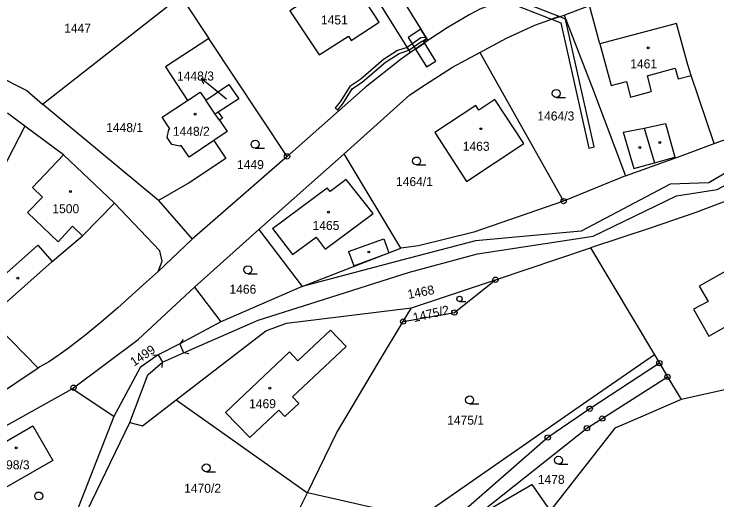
# Model space of a CAD drawing. Extents: x -562167 to -556918, y -1077891 to -1070763.
# Drawn here: x -559876 to -559743.6, y -1075522.9 to -1075431.3 of the extents above; entities that cross this region are included whole.
import ezdxf

# ---------------------------------------------------------------- set-up
doc = ezdxf.new("R2010")
doc.units = 0
for name, color, linetype in [('Hranice parcel', 7, 'Continuous'), ('Parcelní čísla', 7, 'Continuous'), ('Pop  PČ popisy', 7, 'Continuous'), ('Vnitřní kresba', 7, 'Continuous'), ('Věcná břemena k části', 7, 'Continuous'), ('Značky bodu BP', 7, 'Continuous'), ('Značky budov', 7, 'Continuous'), ('Značky kultur', 7, 'Continuous')]:
    doc.layers.add(name, color=color, linetype=linetype)

msp = doc.modelspace()

# ---------------------------------------------------------------- linework, layer by layer
at = {"layer": 'Hranice parcel'}
for p, q in [((-559801.37, -1075438.56), (-559818.39, -1075410.87)), ((-559809.43, -1075417.79), (-559798.08, -1075436.28)), ((-559870.69, -1075448.28), (-559844.66, -1075427.85)), ((-559843.8, -1075429.15), (-559839.36, -1075435.87)), ((-559772.38, -1075431.46), (-559767.63, -1075429.64)), ((-559824.6, -1075458.14), (-559839.36, -1075435.87)), ((-559798.08, -1075436.28), (-559801.37, -1075438.56)), ((-559788.28, -1075438.52), (-559772.5, -1075466.57)), ((-559848.8, -1075466.47), (-559870.69, -1075448.28)), ((-559874.03, -1075452.42), (-559877.3, -1075449.98)), ((-559829.9, -1075471.94), (-559813.82, -1075457.67)), ((-559803.17, -1075475.47), (-559813.82, -1075457.67)), ((-559824.6, -1075458.14), (-559842.46, -1075473.73)), ((-559760.86, -1075461.82), (-559772.5, -1075466.57)), ((-559848.8, -1075466.47), (-559842.46, -1075473.73)), ((-559842.06, -1075482.79), (-559829.9, -1075471.94)), ((-559829.9, -1075471.94), (-559821.79, -1075482.69)), ((-559842.46, -1075473.73), (-559848.9, -1075479.82)), ((-559785.33, -1075481.4), (-559767.4, -1075475.38)), ((-559767.4, -1075475.38), (-559755.39, -1075495.58)), ((-559801.18, -1075486.71), (-559785.33, -1075481.4)), ((-559842.06, -1075482.79), (-559837.1, -1075489.33)), ((-559821.79, -1075482.69), (-559837.1, -1075489.33)), ((-559802.73, -1075489.29), (-559801.18, -1075486.71)), ((-559871.53, -1075498.07), (-559879.99, -1075489.41)), ((-559837.1, -1075489.33), (-559844.81, -1075493.49)), ((-559844.81, -1075493.49), (-559848.92, -1075495.59)), ((-559848.09, -1075496.98), (-559844.1, -1075495.21)), ((-559755.39, -1075495.58), (-559754.46, -1075497.14)), ((-559754.46, -1075497.14), (-559752.93, -1075499.72)), ((-559725.73, -1075498.45), (-559750.37, -1075504.02)), ((-559752.93, -1075499.72), (-559750.37, -1075504.02)), ((-559892.97, -1075517.55), (-559865.07, -1075501.96)), ((-559857.26, -1075507.2), (-559865.07, -1075501.96)), ((-559845.5, -1075504.05), (-559820.78, -1075521.58))]:
    msp.add_line(p, q, dxfattribs=at)
for points in [[(-559672.17, -1075401.69), (-559678.82, -1075405.17), (-559687.43, -1075414.69), (-559699.21, -1075431.72), (-559711.22, -1075442.31), (-559725.64, -1075451.62), (-559745.16, -1075463.14), (-559752.41, -1075463.36), (-559769.21, -1075472.22), (-559789.12, -1075474.06), (-559802.78, -1075477.67), (-559821.79, -1075482.69)], [(-559807.22, -1075432.78), (-559813.19, -1075423.62), (-559824.1, -1075430.68), (-559818.53, -1075439), (-559813.04, -1075435.43), (-559812.51, -1075436.27), (-559807.22, -1075432.78)], [(-559782.91, -1075428.25), (-559788.31, -1075430.38), (-559790.19, -1075431.34), (-559794.42, -1075433.88), (-559798.08, -1075436.28)], [(-559744.13, -1075455.73), (-559748.49, -1075442.88), (-559749.06, -1075440.84), (-559751.22, -1075433.03), (-559765.68, -1075436.89), (-559767.63, -1075429.64)], [(-559788.28, -1075438.52), (-559783.27, -1075435.82), (-559777.89, -1075433.37), (-559775.09, -1075432.34), (-559772.38, -1075431.46)], [(-559772.38, -1075431.46), (-559766.84, -1075445.76), (-559760.86, -1075461.82)], [(-559839.36, -1075435.87), (-559847.51, -1075441.23), (-559843.36, -1075447.56)], [(-559887.86, -1075437.63), (-559885.09, -1075439.61), (-559879.78, -1075442.62), (-559873.64, -1075445.72), (-559870.69, -1075448.28)], [(-559801.37, -1075438.56), (-559803.04, -1075439.72), (-559809.91, -1075445.14), (-559824.6, -1075458.14)], [(-559813.82, -1075457.67), (-559801.47, -1075446.51), (-559798.53, -1075444.57), (-559793.46, -1075441.32), (-559788.28, -1075438.52)], [(-559839.94, -1075447.54), (-559839.56, -1075447.28), (-559835.58, -1075444.55), (-559833.67, -1075447.28), (-559837.59, -1075449.81)], [(-559744.13, -1075455.73), (-559741, -1075454.58), (-559727.67, -1075445.41)], [(-559843.36, -1075447.56), (-559841, -1075445.99), (-559839.94, -1075447.54)], [(-559838.4, -1075455.13), (-559843.08, -1075458.27), (-559844.57, -1075456.05), (-559844.78, -1075456.19), (-559846.32, -1075455.89), (-559847.17, -1075454.56), (-559846.87, -1075453.08), (-559846.67, -1075452.95), (-559848.15, -1075450.75), (-559843.36, -1075447.56)], [(-559837.59, -1075449.81), (-559838.13, -1075450.16), (-559839.94, -1075447.54)], [(-559789.01, -1075448.56), (-559796.77, -1075453.62), (-559790.77, -1075462.85), (-559779.99, -1075455.73), (-559785.43, -1075447.41), (-559788.46, -1075449.39), (-559789.01, -1075448.56)], [(-559837.59, -1075449.81), (-559836.79, -1075450.95), (-559837.34, -1075451.32), (-559835.87, -1075453.44), (-559838.4, -1075455.13)], [(-559874.03, -1075452.42), (-559877.37, -1075458.89), (-559882, -1075465.36), (-559886.93, -1075468.85), (-559882.21, -1075475.68), (-559886.64, -1075478.78), (-559881.95, -1075484.08), (-559879.25, -1075487.14), (-559868.87, -1075477.98), (-559863.12, -1075473.13), (-559857.13, -1075466.97)], [(-559857.13, -1075466.97), (-559866.72, -1075457.84), (-559874.03, -1075452.42)], [(-559844.1, -1075495.21), (-559830.08, -1075489.03), (-559818.93, -1075485.49), (-559801.52, -1075479.98), (-559788.72, -1075476.53), (-559766.9, -1075473.16), (-559751.24, -1075465.57), (-559743.59, -1075464.38), (-559725.67, -1075454.86)], [(-559838.4, -1075455.13), (-559836.16, -1075458.53), (-559843.03, -1075463.12), (-559848.8, -1075466.47)], [(-559760.86, -1075461.82), (-559750.16, -1075457.96), (-559744.13, -1075455.73)], [(-559724.34, -1075460.86), (-559728.19, -1075461.37), (-559747.61, -1075468.71), (-559755.99, -1075471.62), (-559767.4, -1075475.38)], [(-559848.9, -1075479.82), (-559848.16, -1075477.93), (-559848.58, -1075475.94), (-559857.13, -1075466.97)], [(-559772.5, -1075466.57), (-559789.39, -1075472.45), (-559799.82, -1075475.03), (-559803.17, -1075475.47)], [(-559821.79, -1075482.69), (-559813.21, -1075479.34), (-559803.17, -1075475.47)], [(-559746.94, -1075482.59), (-559745.27, -1075485.5), (-559748.02, -1075486.98), (-559745.16, -1075492.02), (-559731.16, -1075484.12), (-559734.28, -1075478.52), (-559737.85, -1075480.52), (-559739.19, -1075478.22), (-559746.94, -1075482.59)], [(-559848.9, -1075479.82), (-559851.15, -1075481.85), (-559856.51, -1075486.69), (-559859.61, -1075489.4), (-559862.77, -1075492), (-559864.38, -1075493.27), (-559866.02, -1075494.48), (-559867.72, -1075495.71), (-559869.39, -1075496.81), (-559871.16, -1075497.86), (-559871.53, -1075498.07)], [(-559802.73, -1075489.29), (-559793.08, -1075487.58), (-559785.33, -1075481.4)], [(-559865.07, -1075501.96), (-559864.85, -1075501.77), (-559852.64, -1075492.68), (-559842.06, -1075482.79)], [(-559845.5, -1075504.05), (-559828.61, -1075491.07), (-559824.71, -1075489.61), (-559801.18, -1075486.71)], [(-559820.78, -1075521.58), (-559815.27, -1075510.36), (-559807.18, -1075496.71), (-559802.73, -1075489.29)], [(-559848.92, -1075495.59), (-559852.3, -1075497.99), (-559857.26, -1075507.2)], [(-559755.39, -1075495.58), (-559768.77, -1075504.82), (-559799.73, -1075526.36), (-559820.78, -1075521.58)], [(-559854.23, -1075508.35), (-559850.81, -1075499.32), (-559848.09, -1075496.98)], [(-559754.46, -1075497.14), (-559767.58, -1075505.74), (-559775.48, -1075511.17), (-559798.39, -1075531.22), (-559818.07, -1075554.51), (-559842.92, -1075588.88)], [(-559871.53, -1075498.07), (-559880.01, -1075503.73), (-559895.62, -1075511.47)], [(-559789.72, -1075526.6), (-559768.11, -1075509.41), (-559765.22, -1075507.59), (-559752.93, -1075499.72)], [(-559854.23, -1075508.35), (-559851.86, -1075508.94), (-559845.5, -1075504.05)], [(-559750.37, -1075504.02), (-559759.46, -1075507.96), (-559762.85, -1075509.43), (-559775, -1075525)], [(-559857.26, -1075507.2), (-559866.01, -1075529.69), (-559876.3, -1075544.73)], [(-559881.72, -1075512.6), (-559879.77, -1075513.16), (-559872.5, -1075508.99), (-559868.74, -1075515.48), (-559879.42, -1075521.63), (-559883.16, -1075515.12), (-559882.31, -1075514.62), (-559881.72, -1075512.6)], [(-559868.91, -1075538.86), (-559864.19, -1075529.04), (-559854.23, -1075508.35)], [(-559789.72, -1075526.6), (-559778.5, -1075520.02), (-559775, -1075525)], [(-559825.48, -1075531.19), (-559823.87, -1075527.87), (-559820.78, -1075521.58)]]:
    msp.add_lwpolyline(points, dxfattribs=at)
at = {"layer": 'Pop  PČ popisy'}
for p, q in [((-559838.48, -1075445.34), (-559840.81, -1075443.45)), ((-559840.81, -1075443.45), (-559839.72, -1075443.69)), ((-559840.81, -1075443.45), (-559840.35, -1075444.47)), ((-559836.01, -1075447.35), (-559838.48, -1075445.34))]:
    msp.add_line(p, q, dxfattribs=at)
at = {"layer": 'Vnitřní kresba'}
for p, q in [((-559765.68, -1075436.89), (-559763.56, -1075444.77)), ((-559756.77, -1075442.93), (-559751.46, -1075441.49)), ((-559751.46, -1075441.49), (-559750.91, -1075443.53)), ((-559756.77, -1075442.93), (-559755.97, -1075445.87)), ((-559750.91, -1075443.53), (-559748.49, -1075442.88)), ((-559763.56, -1075444.77), (-559760.67, -1075443.99)), ((-559760.67, -1075443.99), (-559759.87, -1075446.93)), ((-559759.87, -1075446.93), (-559755.97, -1075445.87)), ((-559837.34, -1075451.32), (-559838.13, -1075450.16)), ((-559757.34, -1075452.78), (-559753.32, -1075451.95)), ((-559753.32, -1075451.95), (-559751.54, -1075458.25)), ((-559761.29, -1075453.58), (-559757.34, -1075452.78)), ((-559761.29, -1075453.58), (-559759.24, -1075460.43)), ((-559757.34, -1075452.78), (-559755.39, -1075459.34)), ((-559872.58, -1075464.01), (-559866.72, -1075457.84)), ((-559755.39, -1075459.34), (-559751.54, -1075458.25)), ((-559759.24, -1075460.43), (-559755.39, -1075459.34)), ((-559813.45, -1075462.48), (-559816.5, -1075464.77)), ((-559808.41, -1075468.89), (-559813.45, -1075462.48)), ((-559872.58, -1075464.01), (-559870.71, -1075465.82)), ((-559827.34, -1075471.76), (-559817.05, -1075464.05)), ((-559816.5, -1075464.77), (-559817.05, -1075464.05)), ((-559873.52, -1075468.73), (-559870.71, -1075465.82)), ((-559873.52, -1075468.73), (-559867.72, -1075474.23)), ((-559817.42, -1075475.64), (-559808.41, -1075468.89)), ((-559867.72, -1075474.23), (-559865.05, -1075471.29)), ((-559865.05, -1075471.29), (-559863.12, -1075473.13)), ((-559827.34, -1075471.76), (-559823.56, -1075476.67)), ((-559823.56, -1075476.67), (-559819.15, -1075473.37)), ((-559819.15, -1075473.37), (-559817.42, -1075475.64)), ((-559881.95, -1075484.08), (-559871.54, -1075474.86)), ((-559871.54, -1075474.86), (-559868.87, -1075477.98)), ((-559813, -1075476.08), (-559806.36, -1075473.66)), ((-559806.36, -1075473.66), (-559805.4, -1075476.3)), ((-559813, -1075476.08), (-559812.04, -1075478.76)), ((-559812.04, -1075478.76), (-559805.4, -1075476.3)), ((-559822.55, -1075496.68), (-559816.39, -1075490.93)), ((-559816.39, -1075490.93), (-559813.49, -1075493.99)), ((-559844.19, -1075492.7), (-559844.81, -1075493.49)), ((-559844.81, -1075493.49), (-559844.1, -1075495.21)), ((-559823.55, -1075503.51), (-559813.49, -1075493.99)), ((-559849.92, -1075495.66), (-559848.92, -1075495.59)), ((-559848.92, -1075495.59), (-559848.09, -1075496.98)), ((-559843.11, -1075495.37), (-559844.1, -1075495.21)), ((-559836.19, -1075506.44), (-559824.17, -1075494.98)), ((-559824.17, -1075494.98), (-559822.55, -1075496.68)), ((-559848.14, -1075497.98), (-559848.09, -1075496.98)), ((-559823.55, -1075503.51), (-559822.38, -1075504.75)), ((-559825, -1075507.21), (-559822.38, -1075504.75)), ((-559836.19, -1075506.44), (-559831.65, -1075511.16)), ((-559831.65, -1075511.16), (-559826.16, -1075505.98)), ((-559826.16, -1075505.98), (-559825, -1075507.21))]:
    msp.add_line(p, q, dxfattribs=at)
at = {"layer": 'Věcná břemena k části'}
for points in [[(-559774.81, -1075432.25), (-559773.32, -1075431.76), (-559782.57, -1075428.11), (-559782.91, -1075428.25), (-559783.92, -1075428.65)], [(-559773.32, -1075431.76), (-559774.81, -1075432.25), (-559773.02, -1075432.96), (-559767.73, -1075456.55), (-559766.75, -1075456.33), (-559772.16, -1075432.22)], [(-559801.78, -1075435.71), (-559800.41, -1075437.9), (-559798.73, -1075436.73), (-559798.98, -1075436.33), (-559798.32, -1075435.89), (-559799.39, -1075434.15)], [(-559799.43, -1075435.79), (-559801.97, -1075437.58), (-559801.65, -1075438.1), (-559799.22, -1075436.37), (-559798.08, -1075436.28), (-559798.44, -1075435.7)], [(-559806.06, -1075440.36), (-559803.51, -1075438.7), (-559801.65, -1075438.1), (-559801.97, -1075437.58), (-559803.77, -1075438.15), (-559806.42, -1075439.88), (-559810.72, -1075443.58), (-559812.77, -1075444.93), (-559814.6, -1075447.84), (-559815.57, -1075449), (-559815.11, -1075449.39), (-559814.11, -1075448.19), (-559812.33, -1075445.36), (-559810.36, -1075444.06)], [(-559796.6, -1075440.15), (-559798.73, -1075436.73), (-559800.41, -1075437.9), (-559798.33, -1075441.23)]]:
    msp.add_lwpolyline(points, close=True, dxfattribs=at)
at = {"layer": 'Značky bodu BP'}
for centre, radius in [((-559824.6, -1075458.14), 0.5), ((-559824.6, -1075458.14), 0.0303), ((-559772.5, -1075466.57), 0.5), ((-559772.5, -1075466.57), 0.0303), ((-559785.33, -1075481.4), 0.5), ((-559785.33, -1075481.4), 0.0303), ((-559793.08, -1075487.58), 0.5), ((-559793.08, -1075487.58), 0.0303), ((-559802.73, -1075489.29), 0.5), ((-559802.73, -1075489.29), 0.0303), ((-559754.46, -1075497.14), 0.5), ((-559754.46, -1075497.14), 0.0303), ((-559752.93, -1075499.72), 0.5), ((-559752.93, -1075499.72), 0.0303), ((-559864.85, -1075501.77), 0.5), ((-559864.85, -1075501.77), 0.0303), ((-559767.58, -1075505.74), 0.5), ((-559767.58, -1075505.74), 0.0303), ((-559765.22, -1075507.59), 0.5), ((-559765.22, -1075507.59), 0.0303), ((-559768.11, -1075509.41), 0.5), ((-559768.11, -1075509.41), 0.0303), ((-559775.48, -1075511.17), 0.5), ((-559775.48, -1075511.17), 0.0303)]:
    msp.add_circle(centre, radius, dxfattribs=at)
at = {"layer": 'Značky budov'}
for centre in [(-559756.54, -1075437.66), (-559841.94, -1075450.15), (-559788.1, -1075452.91), (-559758.15, -1075456.46), (-559754.37, -1075455.5), (-559865.43, -1075464.77), (-559816.8, -1075468.66), (-559809.19, -1075476.17), (-559875.33, -1075481.12), (-559827.86, -1075501.86), (-559875.62, -1075513.1)]:
    msp.add_circle(centre, 0.175, dxfattribs=at)
at = {"layer": 'Značky kultur'}
for p, q in [((-559773.89, -1075447.01), (-559772.14, -1075447.01)), ((-559830.62, -1075456.6), (-559828.87, -1075456.6)), ((-559800.19, -1075459.75), (-559798.44, -1075459.75)), ((-559831.99, -1075480.26), (-559830.24, -1075480.26)), ((-559792.11, -1075485.5), (-559790.94, -1075485.5)), ((-559790.22, -1075504.83), (-559788.47, -1075504.83)), ((-559773.46, -1075516.2), (-559771.71, -1075516.2)), ((-559839.83, -1075517.64), (-559838.08, -1075517.64))]:
    msp.add_line(p, q, dxfattribs=at)
for centre, radius in [((-559773.89, -1075446.26), 0.75), ((-559830.62, -1075455.85), 0.75), ((-559800.19, -1075459), 0.75), ((-559831.99, -1075479.51), 0.75), ((-559792.12, -1075485), 0.502), ((-559790.22, -1075504.08), 0.75), ((-559773.46, -1075515.45), 0.75), ((-559839.83, -1075516.89), 0.75), ((-559871.4, -1075522.2), 0.75)]:
    msp.add_circle(centre, radius, dxfattribs=at)

# ---------------------------------------------------------------- texts
at = {"layer": 'Parcelní čísla'}
for s, p in [('1451', (-559818.22, -1075433.24)), ('1447', (-559866.6, -1075434.79)), ('1461', (-559759.94, -1075441.51)), ('1448/3', (-559845.34, -1075443.82)), ('1464/3', (-559777.44, -1075451.36)), ('1448/1', (-559858.69, -1075453.55)), ('1448/2', (-559846.13, -1075454.25)), ('1463', (-559791.5, -1075457.07)), ('1449', (-559834.04, -1075460.53)), ('1464/1', (-559804.08, -1075463.74)), ('1500', (-559868.83, -1075468.85)), ('1465', (-559819.8, -1075472.01)), ('1466', (-559835.46, -1075484.04)), ('1469', (-559831.76, -1075505.64)), ('1475/1', (-559794.44, -1075508.74)), ('1498/3', (-559880.08, -1075517.17)), ('1478', (-559777.36, -1075519.92)), ('1470/2', (-559844, -1075521.6))]:
    msp.add_text(s, height=1.7, dxfattribs=at).set_placement(p)
for s, rotation, p in [('1468', 11, (-559801.71, -1075485.03)), ('1475/2', 13, (-559800.67, -1075489.41)), ('1499', 34, (-559853.44, -1075497.82))]:
    msp.add_text(s, height=1.7, rotation=rotation, dxfattribs=at).set_placement(p)

doc.saveas('drawing.dxf')
